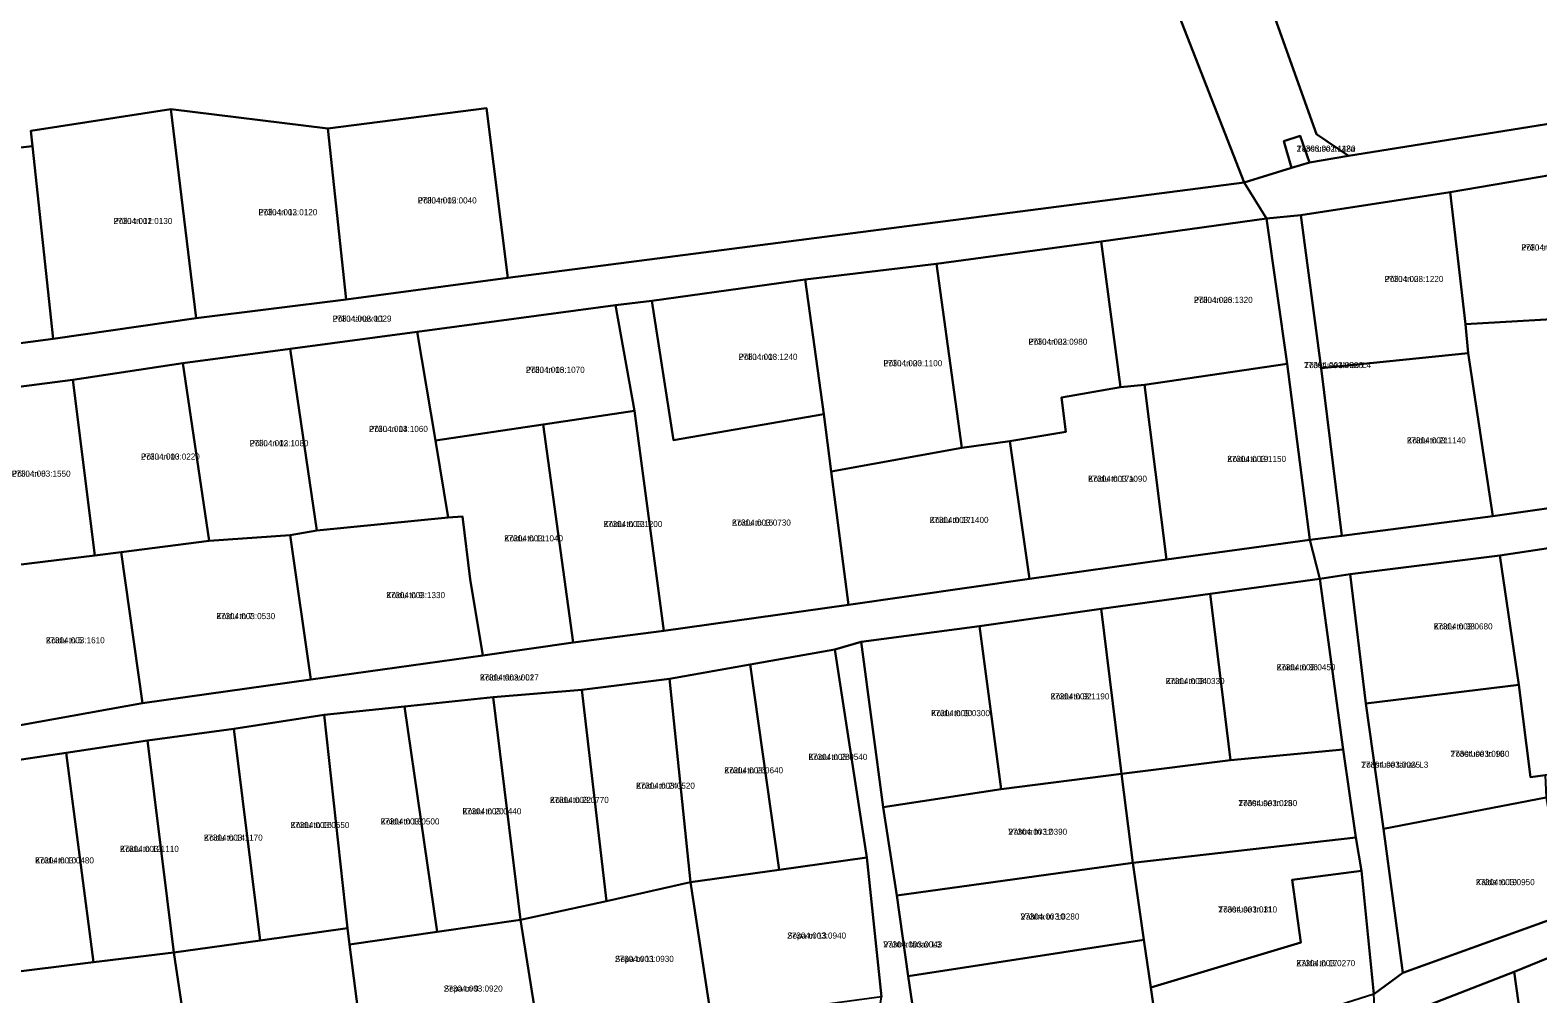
# Model space of a CAD drawing. Extents: x 603789 to 628102, y 6569852 to 6597259.
# Drawn here: x 621695.7 to 622067.3, y 6579923.2 to 6580160.8 of the extents above; entities that cross this region are included whole.
import ezdxf

# ---------------------------------------------------------------- set-up
doc = ezdxf.new("R2010")
doc.units = 0
for name, color, linetype in [('L_AADRESS', 7, 'Continuous'), ('PIIR', 7, 'Continuous'), ('TUNNUS', 7, 'Continuous')]:
    doc.layers.add(name, color=color, linetype=linetype)

msp = doc.modelspace()

# ---------------------------------------------------------------- linework, layer by layer
at = {"layer": 'PIIR'}
for points in [[(621561.07, 6580201.07), (621569.62, 6580200.19), (621624.03, 6580224.85), (621658.39, 6580238.03), (621694.81, 6580251.46), (621727.02, 6580264.69), (621739.07, 6580246.96), (621753.91, 6580245.54), (621783.06, 6580222.46), (621801.5, 6580175.47), (621968.88, 6580190.11), (621994.94, 6580123.23), (621813.44, 6580099.76), (621808.11, 6580141.59), (621769.01, 6580136.55), (621730.33, 6580141.38), (621695.82, 6580136), (621696.23, 6580132.2), (621660.81, 6580128.37), (621660.36, 6580132.13), (621625.52, 6580128.09), (621595.88, 6580123.5), (621588.83, 6580141.47)], [(621991.46, 6580194.84), (622015.82, 6580205.41), (622076.05, 6580220.3), (622085.37, 6580140.24), (622020.63, 6580129.82), (622012.74, 6580135.17)], [(621701.33, 6580084.74), (621696.23, 6580132.2), (621695.82, 6580136), (621730.33, 6580141.38), (621736.58, 6580089.8)], [(621730.33, 6580141.38), (621769.01, 6580136.55), (621773.55, 6580094.43), (621736.58, 6580089.8)], [(621808.11, 6580141.59), (621813.44, 6580099.76), (621773.55, 6580094.43), (621769.01, 6580136.55)], [(621666.49, 6580080.07), (621660.81, 6580128.37), (621696.23, 6580132.2), (621701.33, 6580084.74)], [(622004.74, 6580133.47), (622008.72, 6580134.75), (622010.99, 6580128.23), (622006.58, 6580126.91)], [(622045.67, 6580120.9), (622074.66, 6580125.8), (622080.81, 6580090.17), (622049.46, 6580088.32)], [(622008.88, 6580115.2), (622045.67, 6580120.9), (622049.46, 6580088.32), (622050.17, 6580081.18), (622013.87, 6580077.44)], [(621964.4, 6580072.75), (621959.64, 6580108.73), (622000.47, 6580114.39), (622005.5, 6580078.58), (621970.35, 6580073.35)], [(622000.47, 6580114.39), (622008.88, 6580115.2), (622013.87, 6580077.44), (622018.96, 6580036.11), (622011.14, 6580035.11), (622005.5, 6580078.58)], [(621964.4, 6580072.75), (621949.9, 6580070.22), (621950.94, 6580061.75), (621937.17, 6580059.48), (621925.32, 6580057.83), (621919.1, 6580103.17), (621959.64, 6580108.73)], [(621891.29, 6580066.11), (621886.68, 6580099.33), (621919.1, 6580103.17), (621925.32, 6580057.83), (621893.11, 6580051.96)], [(621848.94, 6580094.11), (621886.68, 6580099.33), (621891.29, 6580066.11), (621854.24, 6580059.73)], [(621848.94, 6580094.11), (621854.24, 6580059.73), (621891.29, 6580066.11), (621893.11, 6580051.96), (621897.39, 6580019.13), (621851.88, 6580012.73), (621844.61, 6580066.94), (621839.97, 6580093.02)], [(621791.07, 6580086.41), (621839.97, 6580093.02), (621844.61, 6580066.94), (621822.11, 6580063.55), (621795.54, 6580059.61)], [(622050.17, 6580081.18), (622049.46, 6580088.32), (622080.81, 6580090.17), (622094.42, 6580091.26), (622099.29, 6580047.14), (622056.23, 6580041.01)], [(621759.71, 6580082.21), (621791.07, 6580086.41), (621795.54, 6580059.61), (621798.68, 6580040.62), (621766.29, 6580037.4)], [(621733.26, 6580078.68), (621759.71, 6580082.21), (621766.29, 6580037.4), (621759.75, 6580036.28), (621739.77, 6580034.86)], [(622050.17, 6580081.18), (622056.23, 6580041.01), (622018.96, 6580036.11), (622013.87, 6580077.44)], [(621718.09, 6580032.11), (621711.62, 6580031.29), (621706.18, 6580074.58), (621733.26, 6580078.68), (621739.77, 6580034.86)], [(621970.35, 6580073.35), (622005.5, 6580078.58), (622011.14, 6580035.11), (621975.76, 6580030.27)], [(621670.63, 6580070), (621706.18, 6580074.58), (621711.62, 6580031.29), (621675.8, 6580026.92)], [(621937.17, 6580059.48), (621950.94, 6580061.75), (621949.9, 6580070.22), (621964.4, 6580072.75), (621970.35, 6580073.35), (621975.76, 6580030.27), (621942.03, 6580025.5)], [(621822.11, 6580063.55), (621844.61, 6580066.94), (621851.88, 6580012.73), (621829.48, 6580009.81)], [(621807.27, 6580006.64), (621804.12, 6580025.42), (621802.21, 6580040.86), (621798.68, 6580040.62), (621795.54, 6580059.61), (621822.11, 6580063.55), (621829.48, 6580009.81)], [(621925.32, 6580057.83), (621937.17, 6580059.48), (621942.03, 6580025.5), (621897.39, 6580019.13), (621893.11, 6580051.96)], [(621759.75, 6580036.28), (621766.29, 6580037.4), (621798.68, 6580040.62), (621802.21, 6580040.86), (621804.12, 6580025.42), (621807.27, 6580006.64), (621764.81, 6580000.66)], [(621739.77, 6580034.86), (621759.75, 6580036.28), (621764.81, 6580000.66), (621723.36, 6579994.87), (621718.09, 6580032.11)], [(622065.47, 6579976.6), (622062.62, 6579999.36), (622057.94, 6580031.28), (622079.7, 6580034.57), (622087.26, 6579979.6), (622069.13, 6579977.07)], [(621675.8, 6580026.92), (621711.62, 6580031.29), (621718.09, 6580032.11), (621723.36, 6579994.87), (621680.33, 6579987.16)], [(622021.06, 6580026.66), (622057.94, 6580031.28), (622062.62, 6579999.36), (622024.91, 6579994.79)], [(621986.53, 6580021.85), (622013.59, 6580025.51), (622019.32, 6579983.46), (621991.52, 6579980.78)], [(622013.59, 6580025.51), (622021.06, 6580026.66), (622024.91, 6579994.79), (622029.25, 6579963.89), (622034.01, 6579928.32), (622026.85, 6579923.06), (622023.87, 6579953.51), (622022.41, 6579961.69), (622019.32, 6579983.46)], [(621959.65, 6580018.12), (621986.53, 6580021.85), (621991.52, 6579980.78), (621964.67, 6579977.41)], [(621929.72, 6580013.88), (621959.65, 6580018.12), (621964.67, 6579977.41), (621935, 6579973.67)], [(621900.49, 6580009.99), (621929.72, 6580013.88), (621935, 6579973.67), (621905.92, 6579969.21)], [(621894.05, 6580008.11), (621900.49, 6580009.99), (621905.92, 6579969.21), (621909.28, 6579947.4), (621912.07, 6579927.5), (621917.92, 6579888.13), (621907.16, 6579886.23), (621904.64, 6579916.63), (621905.56, 6579922.4), (621901.9, 6579956.82)], [(621873.14, 6580004.36), (621894.05, 6580008.11), (621901.9, 6579956.82), (621880.3, 6579953.76)], [(621853.22, 6580000.88), (621873.14, 6580004.36), (621880.3, 6579953.76), (621858.43, 6579950.69)], [(621809.82, 6579996.35), (621831.62, 6579998.14), (621837.76, 6579946.06), (621816.55, 6579941.42)], [(621831.62, 6579998.14), (621853.22, 6580000.88), (621858.43, 6579950.69), (621837.76, 6579946.06)], [(622024.91, 6579994.79), (622062.62, 6579999.36), (622065.47, 6579976.6), (622069.13, 6579977.07), (622069.41, 6579971.62), (622029.25, 6579963.89)], [(621773.85, 6579939.38), (621768.1, 6579991.95), (621787.91, 6579994.01), (621796, 6579938.49), (621774.4, 6579935.37)], [(621787.91, 6579994.01), (621809.82, 6579996.35), (621816.55, 6579941.42), (621796, 6579938.49)], [(621745.84, 6579988.53), (621768.1, 6579991.95), (621773.85, 6579939.38), (621752.35, 6579936.36)], [(621724.59, 6579985.62), (621745.84, 6579988.53), (621752.35, 6579936.36), (621731.11, 6579933.34)], [(621682.44, 6579979.29), (621704.49, 6579982.62), (621711.3, 6579930.94), (621688.07, 6579928.13)], [(621704.49, 6579982.62), (621724.59, 6579985.62), (621731.11, 6579933.34), (621711.3, 6579930.94)], [(622022.41, 6579961.69), (621967.5, 6579955.47), (621964.67, 6579977.41), (621991.52, 6579980.78), (622019.32, 6579983.46)], [(621967.5, 6579955.47), (621909.28, 6579947.4), (621905.92, 6579969.21), (621935, 6579973.67), (621964.67, 6579977.41)], [(622029.25, 6579963.89), (622069.41, 6579971.62), (622074.15, 6579942.81), (622034.01, 6579928.32)], [(621970.21, 6579936.48), (621967.5, 6579955.47), (622022.41, 6579961.69), (622023.87, 6579953.51), (622006.73, 6579951.26), (622008.89, 6579935.8), (621971.91, 6579924.77)], [(621858.43, 6579950.69), (621880.3, 6579953.76), (621901.9, 6579956.82), (621905.56, 6579922.4), (621863.61, 6579916.77)], [(621909.28, 6579947.4), (621967.5, 6579955.47), (621970.21, 6579936.48), (621912.07, 6579927.5)], [(621971.91, 6579924.77), (622008.89, 6579935.8), (622006.73, 6579951.26), (622023.87, 6579953.51), (622026.85, 6579923.06), (621974.57, 6579906.47)], [(621816.55, 6579941.42), (621837.76, 6579946.06), (621858.43, 6579950.69), (621863.61, 6579916.77), (621821.33, 6579911.38)], [(621731.11, 6579933.34), (621752.35, 6579936.36), (621773.85, 6579939.38), (621774.4, 6579935.37), (621778.13, 6579906.01), (621736.16, 6579899.33)], [(621774.4, 6579935.37), (621796, 6579938.49), (621816.55, 6579941.42), (621821.33, 6579911.38), (621778.13, 6579906.01)], [(621917.92, 6579888.13), (621912.07, 6579927.5), (621970.21, 6579936.48), (621971.91, 6579924.77), (621974.57, 6579906.47)], [(622061.48, 6579928.59), (622084.25, 6579937.86), (622091.14, 6579889.62), (622091.61, 6579886.88), (622067.85, 6579883.26)], [(621693.12, 6579893.83), (621688.07, 6579928.13), (621711.3, 6579930.94), (621731.11, 6579933.34), (621736.16, 6579899.33)], [(622034.9, 6579918.24), (622061.48, 6579928.59), (622067.85, 6579883.26), (622040.03, 6579879.14)]]:
    msp.add_lwpolyline(points, close=True, dxfattribs=at)
for points in [[(621991.46, 6580194.84), (622012.74, 6580135.17), (622020.63, 6580129.82), (622010.99, 6580128.23), (622008.72, 6580134.75), (622004.74, 6580133.47), (622006.58, 6580126.91), (621994.94, 6580123.23), (621968.88, 6580190.11)], [(622074.66, 6580125.8), (622045.67, 6580120.9), (622008.88, 6580115.2), (622000.47, 6580114.39), (621994.94, 6580123.23), (622006.58, 6580126.91), (622010.99, 6580128.23), (622020.63, 6580129.82), (622085.37, 6580140.24)], [(621666.49, 6580080.07), (621701.33, 6580084.74), (621736.58, 6580089.8), (621773.55, 6580094.43), (621813.44, 6580099.76), (621994.94, 6580123.23), (622000.47, 6580114.39), (621959.64, 6580108.73), (621919.1, 6580103.17), (621886.68, 6580099.33), (621848.94, 6580094.11), (621839.97, 6580093.02), (621791.07, 6580086.41), (621759.71, 6580082.21), (621733.26, 6580078.68), (621706.18, 6580074.58), (621670.63, 6580070)], [(622079.7, 6580034.57), (622057.94, 6580031.28), (622021.06, 6580026.66), (622013.59, 6580025.51), (622011.14, 6580035.11), (622018.96, 6580036.11), (622056.23, 6580041.01), (622099.29, 6580047.14)], [(621680.33, 6579987.16), (621723.36, 6579994.87), (621764.81, 6580000.66), (621807.27, 6580006.64), (621829.48, 6580009.81), (621851.88, 6580012.73), (621897.39, 6580019.13), (621942.03, 6580025.5), (621975.76, 6580030.27), (622011.14, 6580035.11), (622013.59, 6580025.51), (621986.53, 6580021.85), (621959.65, 6580018.12), (621929.72, 6580013.88), (621900.49, 6580009.99), (621894.05, 6580008.11), (621873.14, 6580004.36), (621853.22, 6580000.88), (621831.62, 6579998.14), (621809.82, 6579996.35), (621787.91, 6579994.01), (621768.1, 6579991.95), (621745.84, 6579988.53), (621724.59, 6579985.62), (621704.49, 6579982.62), (621682.44, 6579979.29)], [(622084.25, 6579937.86), (622061.48, 6579928.59), (622034.9, 6579918.24), (622027.32, 6579915.69), (622026.85, 6579923.06), (622034.01, 6579928.32), (622074.15, 6579942.81)]]:
    msp.add_lwpolyline(points, dxfattribs=at)

# ---------------------------------------------------------------- texts
at = {"layer": 'L_AADRESS'}
for s, p in [('Tööstuse tn 12a', (622007.87, 6580130.88)), ('Põllu tn 13', (621751.94, 6580115.2)), ('Põllu tn 15', (621791.22, 6580118.1)), ('Põllu tn 11', (621716.2, 6580113.03)), ('Põllu tn 30', (622063.24, 6580106.5)), ('Põllu tn 28', (622029.53, 6580098.73)), ('Põllu tn 26', (621982.52, 6580093.57)), ('Põllu tänav L1', (621770.22, 6580088.95)), ('Põllu tn 22', (621941.75, 6580083.26)), ('Põllu tn 18', (621870.31, 6580079.53)), ('Põllu tn 20', (621906, 6580077.96)), ('Põllu tn 16', (621817.85, 6580076.32)), ('Tööstuse tänav L4', (622009.71, 6580077.49)), ('Põllu tn 14', (621779.2, 6580061.75)), ('Põllu tn 12', (621749.77, 6580058.23)), ('Koidu tn 21', (622035.05, 6580058.92)), ('Põllu tn 10', (621722.98, 6580054.93)), ('Koidu tn 19', (621990.75, 6580054.35)), ('Põllu tn 8', (621691.12, 6580050.72)), ('Koidu tn 17a', (621956.46, 6580049.45)), ('Koidu tn 13', (621837, 6580038.29)), ('Koidu tn 15', (621868.68, 6580038.65)), ('Koidu tn 17', (621917.41, 6580039.3)), ('Koidu tn 11', (621812.51, 6580034.76)), ('Koidu tn 9', (621783.43, 6580020.76)), ('Koidu tn 7', (621741.56, 6580015.58)), ('Koidu tn 38', (622041.66, 6580013.04)), ('Koidu tn 5', (621699.52, 6580009.63)), ('Koidu tänav L1', (621806.53, 6580000.45)), ('Koidu tn 34', (621975.59, 6579999.56)), ('Koidu tn 36', (622002.93, 6580002.97)), ('Koidu tn 32', (621947.2, 6579995.78)), ('Koidu tn 30', (621917.75, 6579991.65)), ('Tööstuse tn 10', (622045.8, 6579981.62)), ('Koidu tn 26', (621866.76, 6579977.55)), ('Koidu tn 28', (621887.52, 6579980.86)), ('Tööstuse tänav L3', (622023.8, 6579978.94)), ('Koidu tn 24', (621845.02, 6579973.76)), ('Koidu tn 22', (621823.79, 6579970.25)), ('Koidu tn 20', (621802.23, 6579967.46)), ('Tööstuse tn 13', (621993.5, 6579969.46)), ('Koidu tn 16', (621759.85, 6579964.05)), ('Koidu tn 18', (621782.05, 6579964.94)), ('Vahtra tn 12', (621936.79, 6579962.4)), ('Koidu tn 14', (621738.47, 6579960.95)), ('Koidu tn 10', (621696.87, 6579955.33)), ('Koidu tn 12', (621717.8, 6579958.17)), ('Kalda tn 19', (622052.04, 6579949.97)), ('Vahtra tn 10', (621939.8, 6579941.49)), ('Tööstuse tn 11', (621988.55, 6579943.23)), ('Sepa tn 13', (621882.29, 6579936.79)), ('Vahtra tänav L3', (621905.98, 6579934.6)), ('Sepa tn 11', (621839.82, 6579931.04)), ('Kalda tn 17', (622007.79, 6579929.99)), ('Sepa tn 9', (621797.62, 6579923.72))]:
    msp.add_text(s, height=1.5, dxfattribs=at).set_placement(p)
at = {"layer": 'TUNNUS'}
for s, p in [('27303:002:1480', (622007.87, 6580130.88)), ('27304:002:0120', (621751.94, 6580115.2)), ('27304:002:0040', (621791.22, 6580118.1)), ('27304:002:0130', (621716.2, 6580113.03)), ('27304:003:0850', (622063.24, 6580106.5)), ('27304:003:1220', (622029.53, 6580098.73)), ('27304:003:1320', (621982.52, 6580093.57)), ('27304:003:0029', (621770.22, 6580088.95)), ('27304:003:0980', (621941.75, 6580083.26)), ('27304:003:1240', (621870.31, 6580079.53)), ('27304:003:1100', (621906, 6580077.96)), ('27304:003:1070', (621817.85, 6580076.32)), ('27304:003:0026', (622009.71, 6580077.49)), ('27304:003:1060', (621779.2, 6580061.75)), ('27304:003:1080', (621749.77, 6580058.23)), ('27304:003:1140', (622035.05, 6580058.92)), ('27304:003:0220', (621722.98, 6580054.93)), ('27304:003:1150', (621990.75, 6580054.35)), ('27304:003:1550', (621691.12, 6580050.72)), ('27304:003:1090', (621956.46, 6580049.45)), ('27304:003:1200', (621837, 6580038.29)), ('27304:003:0730', (621868.68, 6580038.65)), ('27304:003:1400', (621917.41, 6580039.3)), ('27304:003:1040', (621812.51, 6580034.76)), ('27304:003:1330', (621783.43, 6580020.76)), ('27304:003:0530', (621741.56, 6580015.58)), ('27304:003:0680', (622041.66, 6580013.04)), ('27304:003:1610', (621699.52, 6580009.63)), ('27304:003:0027', (621806.53, 6580000.45)), ('27304:003:0330', (621975.59, 6579999.56)), ('27304:003:0450', (622002.93, 6580002.97)), ('27304:003:1190', (621947.2, 6579995.78)), ('27304:003:0300', (621917.75, 6579991.65)), ('27304:003:0960', (622045.8, 6579981.62)), ('27304:003:0640', (621866.76, 6579977.55)), ('27304:003:0540', (621887.52, 6579980.86)), ('27304:003:0025', (622023.8, 6579978.94)), ('27304:003:0520', (621845.02, 6579973.76)), ('27304:003:0770', (621823.79, 6579970.25)), ('27304:003:0440', (621802.23, 6579967.46)), ('27304:003:0260', (621993.5, 6579969.46)), ('27304:003:0550', (621759.85, 6579964.05)), ('27304:003:0500', (621782.05, 6579964.94)), ('27304:003:0390', (621936.79, 6579962.4)), ('27304:003:1170', (621738.47, 6579960.95)), ('27304:003:0480', (621696.87, 6579955.33)), ('27304:003:1110', (621717.8, 6579958.17)), ('27304:003:0950', (622052.04, 6579949.97)), ('27304:003:0280', (621939.8, 6579941.49)), ('27304:003:0310', (621988.55, 6579943.23)), ('27304:003:0940', (621882.29, 6579936.79)), ('27304:003:0043', (621905.98, 6579934.6)), ('27304:003:0930', (621839.82, 6579931.04)), ('27304:003:0270', (622007.79, 6579929.99)), ('27304:003:0920', (621797.62, 6579923.72))]:
    msp.add_text(s, height=1.5, dxfattribs=at).set_placement(p)

doc.saveas('drawing.dxf')
